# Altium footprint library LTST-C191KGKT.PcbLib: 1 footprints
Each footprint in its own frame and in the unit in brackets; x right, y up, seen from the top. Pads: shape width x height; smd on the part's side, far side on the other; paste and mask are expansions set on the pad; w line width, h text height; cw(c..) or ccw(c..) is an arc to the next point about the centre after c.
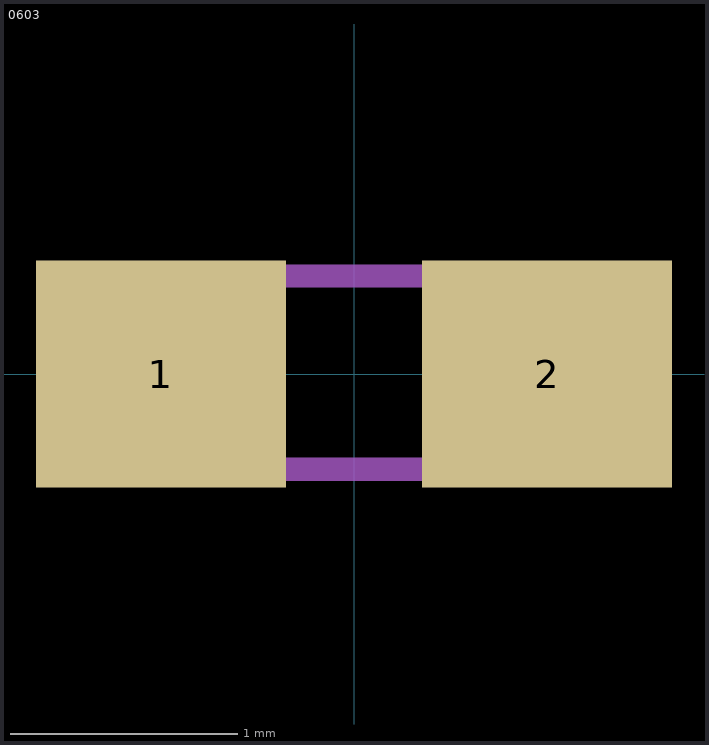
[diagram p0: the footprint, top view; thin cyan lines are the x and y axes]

## 0603 [mm]
pads (2):
  rect 1.1x1 smd: 1(-0.85,0) 2(0.85,0)
Mechanical 13:
  region: 0.83,-0.471 0.331,-0.471 0.331,0.48 0.83,0.48
  region: -0.338,-0.471 -0.84,-0.471 -0.84,0.48 -0.338,0.48
  lines w0.102: -0.356,-0.419 0.356,-0.419 ; -0.356,0.432 0.356,0.432
3D body "step_temp.STEP": height 0.55, standoff 0, extent -0.8,-0.4 0.8,0.4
